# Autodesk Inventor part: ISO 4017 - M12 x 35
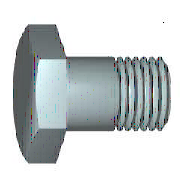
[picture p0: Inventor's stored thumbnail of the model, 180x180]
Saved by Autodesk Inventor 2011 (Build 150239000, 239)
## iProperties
IsCustomPart: 0
Created: 2009-02
Part Number: ISO 4017 - M12 x 35
Material: Stainless Steel, 440C
Description: Hexagon head screws
Document SubType Name: Modeling
Standard: ISO 4017
Designer: V.de Jong
Standard Revision: Third edition 1999-08-15
Standards Organization: ISO
Language: en-US
Size Designation: M12 x 35
Categories: <MemberInstance><Categories><Category DisplayName="Fasteners" InternalName="e4da775c-781d-43d5-af7c-5136215cf5a6" Mnemonic="FSTN"><Category DisplayName="Bolts"
Density: 7.75 g/cm^3
Mass: 46.4851 g
Surface Area: 23.0389 cm^2
Volume: 5.99808 cm^3
Author: V.de Jong
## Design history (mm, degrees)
body "Solid1"
workplane "Work Plane1"
revolve "Body" stored, may be unused: angle "d12" = 90 deg
sketch "Sketch2"
  geometry: L1 (0, 10.392)-(9, 5.196); L2 (9, 5.196)-(9, -5.196); L3 (9, -5.196)-(0, -10.392); L4 (0, -10.392)-(-9, -5.196); L5 (-9, -5.196)-(-9, 5.196); L6 (-9, 5.196)-(0, 10.392); 2 further points
  constraints: 12 end point, 1 coincident, 1 vertical, 11 other
  dimensions: "d11" = 18 distance between parallel lines of L5 L2 (= SW)
extrude "Head" join sketch "Sketch2" distance "d3" = 6.9 (= KOH - SD); taper "d4" = 0 deg
revolve "Chamfer1" stored, may be unused: angle "d21" = 90 deg
feature "Thread" dims "d15" = 29.7 (= GEL), "d16" = 0
chamfer "Chamfer2" distance "d6" = 1.07354 (= -0.5 x SPD + 0.5 x GD); stored, may be unused: second distance "d7" = 1.07364 (computed from GUL), angle "d55" = 45 deg
sketch "Sketch1"
  geometry: L1 (0, 8.315)-(0, 6); L2 (5.3, 6)-(35, 6); L3 (35, 6)-(35, 0); L4 (35, 0)-(-0.6, 0); L5 (-7.72, 0)-(42.12, 0) reference; L6 (-0.6, 0)-(-0.6, 8.315); L7 (-0.6, 8.315)-(0, 8.315); L8 (5.3, 6)-(4.226, 6); L9 (4.226, 6)-(0, 6); L10 (0, -1.663)-(0, 9.978) reference
  constraints: 16 end point, 2 collinear, 2 perpendicular, 1 parallel
  dimensions: "d0" = 35 distance between parallel lines of L3 L1 (= NLG); "d1" = 29.7 distance from line of L2.start L3 (= GEL); "d2" = 12 diameter of L2 L4 (= GD); "d9" = 0.6001 distance between parallel lines of L6 L1 (computed from SD); "d10" = 16.63 diameter of L7 L4 (= SD2); "d13" = 1.07364 distance of L2.start L8.end (computed from GAL); "d14" = 12 diameter of L9 L4 (= BDM)
sketch "Sketch4"
  geometry: L1 (-7.5, 9)-(-7.5, 10.392); L2 (-7.5, 10.392)-(-6.696, 10.392); L3 (-6.696, 10.392)-(-7.5, 9); L4 (-8.88, 0)-(0.78, 0) reference; L5 (-0.6, 10.392)-(-7.5, 10.392) reference; L6 (-7.5, 5.196)-(-7.5, 10.392) reference
  constraints: 6 end point, 2 collinear, 1 perpendicular, 1 vertical
  dimensions: "d5" = 30 deg angle of L3 L1 (= ANG1); "d19" = 18 diameter of L1.start L4 (= SW0)
other parameters: "NLG" = 35 [user parameter; used in 1 equation term], "GD" = 12 (= NND) [user parameter; used in 2 equation terms], "BDM" = 12 (= NND) [user parameter; used in 1 equation term], "KOH" = 7.5 [user parameter; used in 1 equation term], "GEL" = 29.7 [user parameter; used in 2 equation terms], "SW" = 18 [user parameter; used in 2 equation terms], "SW0" = 18 (= SW) [user parameter; used in 1 equation term], "SPD" = 9.85293 (= NND - 1.2269 x PTC) [user parameter; used in 1 equation term], "SD2" = 16.63 [user parameter; used in 2 equation terms], "SD" = 0.6 [user parameter; used in 2 equation terms], "ANG1" = 30 deg [user parameter; used in 1 equation term], "GAL" = 1.07354 (= 0.61345 x PTC) [user parameter; used in 1 equation term], "GUL" = 1.07354 (= 0.61345 x PTC) [user parameter; used in 1 equation term], "d8" = 0, "RR" = 0.6 [user parameter], "d57" = 0, "d58" = 0, "TPU" = 5.71429 (computed from PTC) [user parameter], "GD1" = 9.85293 (= THREADDIA - 1.2269 x PTC) [user parameter], "THREADDIA" = 12 [user parameter; used in 1 equation term], "SDH" = 16.63 (= SD2) [user parameter], "SDHG" = 5.3 [user parameter], "TOA" = 30 deg [user parameter], "PTC" = 1.75 [user parameter; used in 5 equation terms], "NND" = 12 [user parameter; used in 3 equation terms], "E0" = 20.79 [user parameter]
